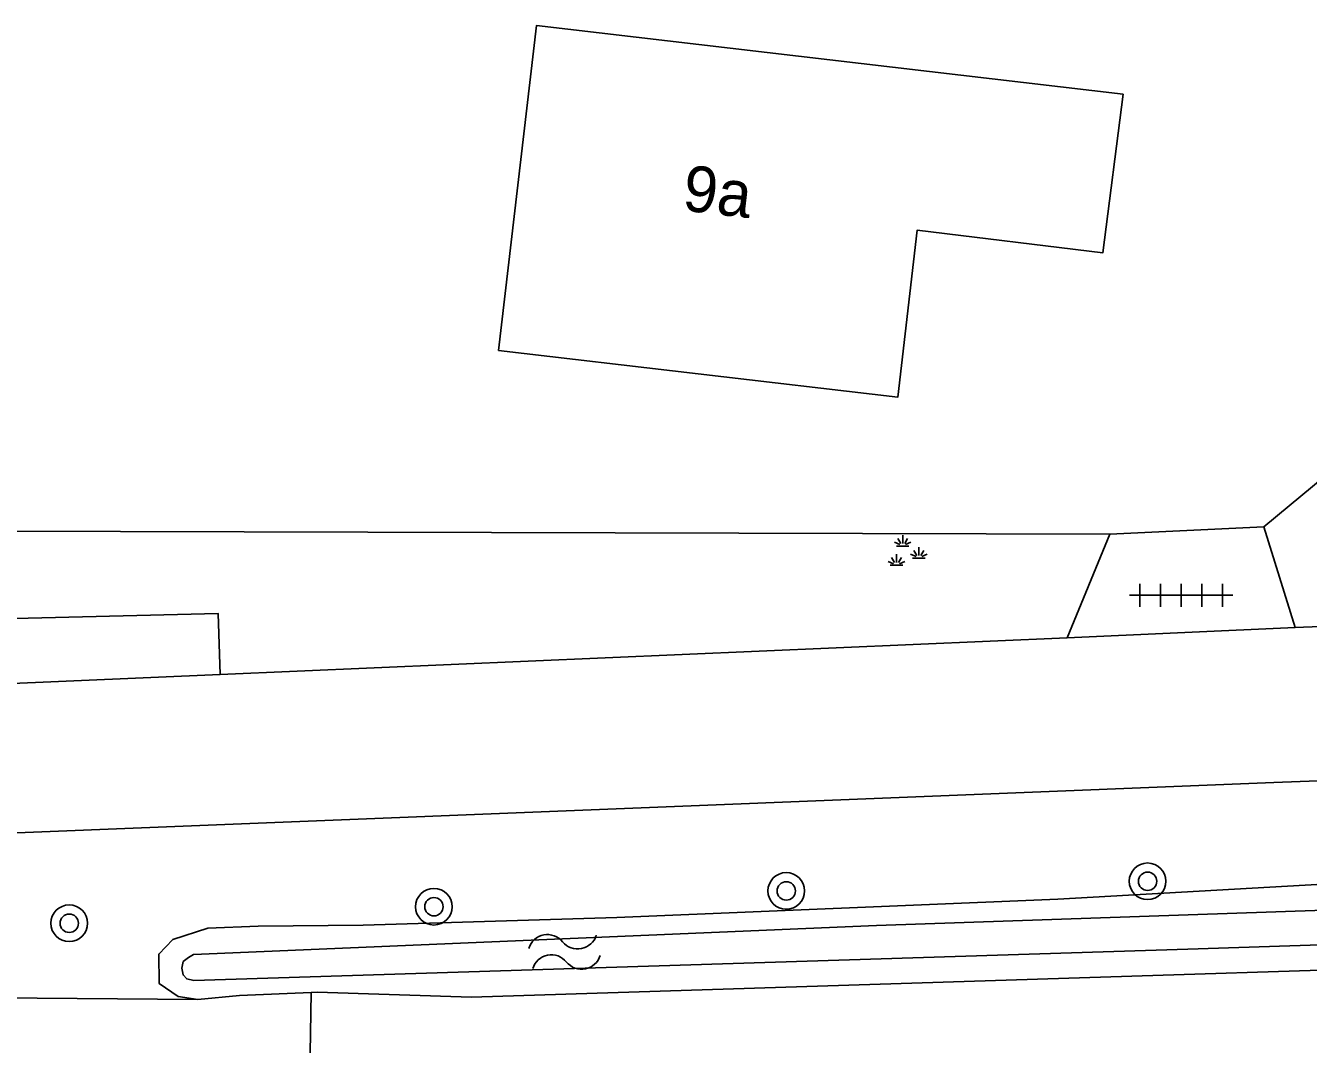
# Model space of a CAD drawing. Extents: x 137000 to 140001, y 403500 to 406000.
# Drawn here: x 138058.21 to 138086.17, y 405535.89 to 405558.11 of the extents above; entities that cross this region are included whole.
import ezdxf

# ---------------------------------------------------------------- set-up
doc = ezdxf.new("R2010")
doc.units = 0
for name, color, linetype in [('gg-afsc-erfafscheiding', 7, 'Continuous'), ('gg-anno-huisnummerreeks BGT', 7, 'Continuous'), ('gg-bbg-gedigitaliseerde bebouwing', 7, 'Continuous'), ('gg-bbg-hoofdgebouw', 7, 'Continuous'), ('gg-knt-bronhoudergrens', 7, 'Continuous'), ('gg-knt-verharding', 7, 'Continuous'), ('gg-kntw-bovenkant insteek waterloop', 7, 'Continuous'), ('gg-kntw-waterlijn', 7, 'Continuous'), ('gt-grn-groengrens', 7, 'Continuous'), ('gt-symb-boom', 7, 'Continuous'), ('gt-symb-groenvak', 7, 'Continuous'), ('gt-symb-tegel verharding', 7, 'Continuous'), ('gt-symb-watersymbool', 7, 'Continuous')]:
    doc.layers.add(name, color=color, linetype=linetype)

# ---------------------------------------------------------------- blocks, each defined once
blk = doc.blocks.new('gt0-WA')
at = {"layer": 'gt-symb-watersymbool'}
for centre, start, end in [((-0.323, 0.022), 28.0725, 151.9275), ((0.427, 0.422), 208.0725, 331.9275), ((-0.323, -0.428), 28.0725, 151.9275), ((0.427, -0.028), 208.0725, 331.9275)]:
    blk.add_arc(centre, 0.425, start, end, dxfattribs=at)
blk = doc.blocks.new('gt0-BOOM')
at = {"layer": 'gt-symb-boom'}
for radius in [0.4, 0.2]:
    blk.add_circle((0, 0), radius, dxfattribs=at)
blk = doc.blocks.new('gt0-GRVAK')
at = {"layer": 'gt-symb-groenvak'}
for p, q in [((-0.091, 0.211), (-0.156, 0.322)), ((-0.047, 0.214), (-0.047, 0.393)), ((-0.004, 0.211), (0.061, 0.322)), ((-0.11, 0.189), (-0.228, 0.24)), ((-0.182, 0.153), (0.088, 0.153)), ((0.015, 0.189), (0.133, 0.24)), ((0.262, -0.052), (0.197, 0.059)), ((0.305, -0.049), (0.305, 0.13)), ((0.349, -0.052), (0.414, 0.059)), ((-0.245, -0.228), (-0.363, -0.177)), ((-0.318, -0.264), (-0.047, -0.264)), ((-0.226, -0.206), (-0.291, -0.095)), ((-0.183, -0.203), (-0.183, -0.024)), ((-0.139, -0.206), (-0.074, -0.095)), ((-0.12, -0.228), (-0.002, -0.177)), ((0.243, -0.074), (0.125, -0.023)), ((0.17, -0.11), (0.441, -0.11)), ((0.368, -0.074), (0.486, -0.023))]:
    blk.add_line(p, q, dxfattribs=at)
blk = doc.blocks.new('gt0-TEG1')
at = {"layer": 'gt-symb-tegel verharding'}
for p, q in [((-1.125, 0), (1.125, 0)), ((-0.9, -0.25), (-0.9, 0.25)), ((-0.45, -0.25), (-0.45, 0.25)), ((0, -0.25), (0, 0.25)), ((0.45, -0.25), (0.45, 0.25)), ((0.9, -0.25), (0.9, 0.25))]:
    blk.add_line(p, q, dxfattribs=at)

msp = doc.modelspace()

# ---------------------------------------------------------------- linework, layer by layer
at = {"layer": 'gg-afsc-erfafscheiding'}
for p, q in [((138085.198, 405547.182), (138086.561, 405548.311)), ((138055.9, 405547.088), (138081.842, 405547.023))]:
    msp.add_line(p, q, dxfattribs=at)
at = {"layer": 'gg-bbg-gedigitaliseerde bebouwing'}
msp.add_lwpolyline([(138082.131, 405556.621), (138069.34, 405558.115), (138068.511, 405551.03)], dxfattribs=at)
at = {"layer": 'gg-bbg-hoofdgebouw'}
msp.add_lwpolyline([(138068.511, 405551.03), (138077.222, 405550.012), (138077.642, 405553.652), (138081.692, 405553.162), (138082.131, 405556.621)], dxfattribs=at)
at = {"layer": 'gg-knt-bronhoudergrens'}
for p, q in [((138054.023, 405536.935), (138061.96, 405536.871)), ((138064.325, 405530.878), (138064.43, 405537.023))]:
    msp.add_line(p, q, dxfattribs=at)
at = {"layer": 'gg-knt-verharding'}
for p, q in [((138085.198, 405547.182), (138081.842, 405547.023)), ((138085.887, 405544.989), (138085.198, 405547.182)), ((138080.914, 405544.762), (138081.842, 405547.023)), ((138140.114, 405547.047), (138085.887, 405544.989)), ((138085.887, 405544.989), (138080.914, 405544.762)), ((138080.914, 405544.762), (138062.446, 405543.963)), ((138062.446, 405543.963), (138055.363, 405543.656))]:
    msp.add_line(p, q, dxfattribs=at)
msp.add_lwpolyline([(138055.471, 405540.044), (138055.611, 405540.068), (138055.822, 405540.421), (138085.415, 405541.607), (138225.992, 405546.925)], dxfattribs=at)
at = {"layer": 'gg-kntw-bovenkant insteek waterloop'}
for points in [[(138061.96, 405536.871), (138061.529, 405536.934), (138061.117, 405537.218), (138061.107, 405537.86), (138061.417, 405538.181), (138062.18, 405538.427), (138063.272, 405538.473), (138065.562, 405538.494), (138071.097, 405538.662), (138080.71, 405539.056), (138095.985, 405539.925)], [(138149.844, 405539.419), (138149.46, 405539.343), (138148.451, 405539.305), (138147.3, 405539.232), (138145.107, 405539.139), (138139.463, 405539.108), (138134.655, 405539.042), (138067.924, 405536.919), (138064.562, 405537.028), (138064.43, 405537.023)], [(138061.96, 405536.871), (138062.868, 405536.961), (138064.43, 405537.023)]]:
    msp.add_lwpolyline(points, dxfattribs=at)
at = {"layer": 'gg-kntw-waterlijn'}
msp.add_lwpolyline([(138149.574, 405540.127), (138083.544, 405537.965), (138061.875, 405537.285), (138061.716, 405537.321), (138061.637, 405537.408), (138061.608, 405537.552), (138061.637, 405537.696), (138061.752, 405537.79), (138061.867, 405537.855), (138076.753, 405538.486), (138126.87, 405540.2), (138149.422, 405540.964), (138149.639, 405540.877), (138149.732, 405540.726), (138149.761, 405540.466), (138149.711, 405540.257), (138149.574, 405540.127)], dxfattribs=at)
at = {"layer": 'gt-grn-groengrens'}
msp.add_lwpolyline([(138055.593, 405545.127), (138062.401, 405545.293), (138062.446, 405543.963)], dxfattribs=at)

# ---------------------------------------------------------------- block references
at = {"layer": 'gt-symb-boom'}
for p in [(138074.788, 405539.239), (138082.666, 405539.449), (138067.106, 405538.895), (138059.155, 405538.534)]:
    msp.add_blockref('gt0-BOOM', p, dxfattribs=at)
at = {"layer": 'gt-symb-groenvak'}
msp.add_blockref('gt0-GRVAK', (138077.374, 405546.606), dxfattribs=at)
at = {"layer": 'gt-symb-tegel verharding'}
msp.add_blockref('gt0-TEG1', (138083.4, 405545.689), dxfattribs=at)
at = {"layer": 'gt-symb-watersymbool', "rotation": 11.00666417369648}
msp.add_blockref('gt0-WA', (138069.902, 405537.902), dxfattribs=at)

# ---------------------------------------------------------------- texts
at = {"layer": 'gg-anno-huisnummerreeks BGT'}
msp.add_text('9a', height=1, rotation=353.3, dxfattribs=at).set_placement((138072.5, 405554.088))

doc.saveas('drawing.dxf')
